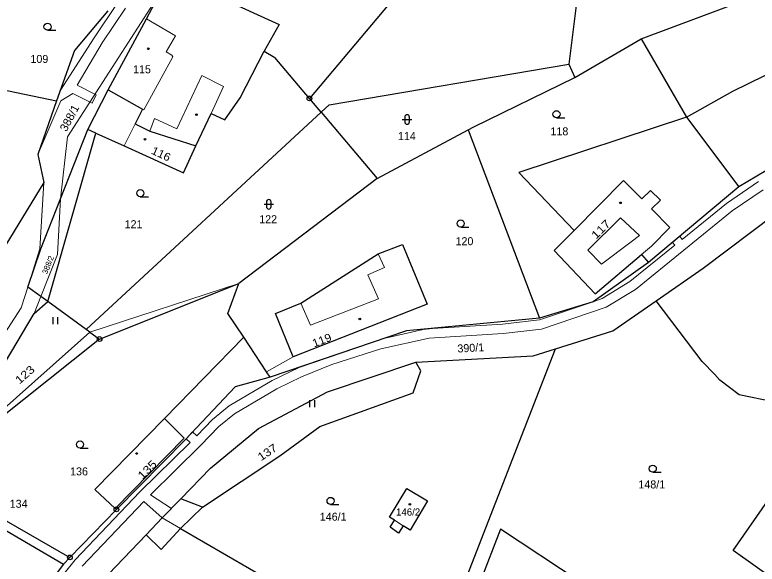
# Model space of a CAD drawing. Extents: x -504006 to -501322, y -1128098 to -1124665.
# Drawn here: x -502579.9 to -502422.2, y -1126531.9 to -1126415.1 of the extents above; entities that cross this region are included whole.
import ezdxf
from ezdxf.enums import TextEntityAlignment as Align

# ---------------------------------------------------------------- set-up
doc = ezdxf.new("R2010")
doc.units = 0
doc.header["$LTSCALE"] = 0.68
for name, color, linetype, lineweight in [('1', 7, 'Continuous', 25), ('13', 7, 'Continuous', 13), ('3', 7, 'Continuous', 25), ('4', 7, 'Continuous', 13), ('5', 7, 'Continuous', 25), ('8', 7, 'Continuous', 25)]:
    doc.layers.add(name, color=color, linetype=linetype, lineweight=lineweight)
doc.layers.add('2', color=7, linetype='Continuous')

msp = doc.modelspace()

# ---------------------------------------------------------------- linework, layer by layer
at = {"layer": '1'}
for p, q in [((-502488.63, -1126398.78), (-502517.33, -1126432.89)), ((-502459.24, -1126402.04), (-502462.2, -1126425.6)), ((-502446.8, -1126420.25), (-502404.96, -1126404.48)), ((-502546.11, -1126406.89), (-502523.76, -1126417.19)), ((-502551.92, -1126415.99), (-502549, -1126410.36)), ((-502560.18, -1126414.25), (-502562.43, -1126416.93)), ((-502560.09, -1126431.07), (-502551.92, -1126415.99)), ((-502562.43, -1126416.93), (-502567.25, -1126422.67)), ((-502523.76, -1126417.19), (-502526.92, -1126422.81)), ((-502460.9, -1126428.42), (-502446.8, -1126420.25)), ((-502446.8, -1126420.25), (-502437.18, -1126436.87)), ((-502567.25, -1126422.67), (-502571.03, -1126433.39)), ((-502532.06, -1126432.78), (-502526.92, -1126422.81)), ((-502526.92, -1126422.81), (-502524.65, -1126424.22)), ((-502517.33, -1126432.89), (-502524.65, -1126424.22)), ((-502513.12, -1126434.23), (-502462.2, -1126425.6)), ((-502462.2, -1126425.6), (-502460.9, -1126428.42)), ((-502482.37, -1126438.94), (-502460.9, -1126428.42)), ((-502582.93, -1126430.94), (-502571.03, -1126433.39)), ((-502564.42, -1126439.51), (-502560.09, -1126431.07)), ((-502560.09, -1126431.07), (-502552.75, -1126435.16)), ((-502571.03, -1126433.39), (-502575.04, -1126444.78)), ((-502535.29, -1126437.44), (-502532.06, -1126432.78)), ((-502514.85, -1126435.83), (-502517.33, -1126432.89)), ((-502552.75, -1126435.16), (-502554.32, -1126438.26)), ((-502514.85, -1126435.83), (-502513.12, -1126434.23)), ((-502564.75, -1126481.99), (-502514.85, -1126435.83)), ((-502541.42, -1126442.95), (-502538.21, -1126436.07)), ((-502538.21, -1126436.07), (-502535.29, -1126437.44)), ((-502514.85, -1126435.83), (-502502.96, -1126449.91)), ((-502554.32, -1126438.26), (-502551.25, -1126439.82)), ((-502437.18, -1126436.87), (-502472.85, -1126448.67)), ((-502437.18, -1126436.87), (-502426.09, -1126451.69)), ((-502570.21, -1126454.22), (-502564.42, -1126439.51)), ((-502562.71, -1126440.28), (-502564.42, -1126439.51)), ((-502551.25, -1126439.82), (-502541.42, -1126442.95)), ((-502502.96, -1126449.91), (-502483.59, -1126439.59)), ((-502483.59, -1126439.59), (-502482.37, -1126438.94)), ((-502483.59, -1126439.59), (-502468.46, -1126479.6)), ((-502572.9, -1126476.08), (-502562.71, -1126440.28)), ((-502562.71, -1126440.28), (-502556.71, -1126442.98)), ((-502556.71, -1126442.98), (-502544.09, -1126448.68)), ((-502544.09, -1126448.68), (-502541.42, -1126442.95)), ((-502414.39, -1126444.68), (-502426.09, -1126451.69)), ((-502575.04, -1126444.78), (-502573.73, -1126450.8)), ((-502472.85, -1126448.67), (-502461.08, -1126460.97)), ((-502573.73, -1126450.8), (-502598.36, -1126490.94)), ((-502502.96, -1126449.91), (-502532.33, -1126472.27)), ((-502426.09, -1126451.69), (-502445.3, -1126467.77)), ((-502433.67, -1126469.01), (-502413.48, -1126453.7)), ((-502574.42, -1126464.9), (-502570.21, -1126454.22)), ((-502461.08, -1126460.97), (-502465.3, -1126465.24)), ((-502577.17, -1126472.99), (-502574.42, -1126464.9)), ((-502502.72, -1126465.95), (-502497.55, -1126463.94)), ((-502497.55, -1126463.94), (-502492.28, -1126476.61)), ((-502519.13, -1126476.45), (-502502.72, -1126465.95)), ((-502465.3, -1126465.24), (-502456.61, -1126474.42)), ((-502456.61, -1126474.42), (-502446.76, -1126466.1)), ((-502446.76, -1126466.1), (-502445.3, -1126467.77)), ((-502445.3, -1126467.77), (-502457.01, -1126476.15)), ((-502443.65, -1126475.9), (-502433.67, -1126469.01)), ((-502574.4, -1126474.99), (-502577.17, -1126472.99)), ((-502561.92, -1126484.04), (-502532.33, -1126472.27)), ((-502534.63, -1126478.58), (-502532.33, -1126472.27)), ((-502575.83, -1126478.59), (-502572.9, -1126476.08)), ((-502572.9, -1126476.08), (-502574.4, -1126474.99)), ((-502564.75, -1126481.99), (-502572.9, -1126476.08)), ((-502457.01, -1126476.15), (-502468.46, -1126479.6)), ((-502452.88, -1126482.27), (-502443.65, -1126475.9)), ((-502433.88, -1126488.84), (-502443.65, -1126475.9)), ((-502524.53, -1126478.59), (-502519.13, -1126476.45)), ((-502492.28, -1126476.61), (-502520.78, -1126487.82)), ((-502581.9, -1126488.91), (-502575.83, -1126478.59)), ((-502531.27, -1126483.66), (-502534.63, -1126478.58)), ((-502520.78, -1126487.82), (-502524.53, -1126478.59)), ((-502468.46, -1126479.6), (-502496.7, -1126482.33)), ((-502563.94, -1126482.57), (-502564.75, -1126481.99)), ((-502496.7, -1126482.33), (-502525.65, -1126492.16)), ((-502465.06, -1126486.12), (-502452.88, -1126482.27)), ((-502561.92, -1126484.04), (-502598.32, -1126513.14)), ((-502563.94, -1126482.57), (-502561.92, -1126484.04)), ((-502548.11, -1126500.91), (-502531.27, -1126483.66)), ((-502526.42, -1126490.99), (-502531.27, -1126483.66)), ((-502491.56, -1126554.34), (-502465.06, -1126486.12)), ((-502469.78, -1126487.61), (-502465.06, -1126486.12)), ((-502494.74, -1126488.95), (-502469.78, -1126487.61)), ((-502431.19, -1126491.59), (-502433.88, -1126488.84)), ((-502513.47, -1126495.29), (-502494.74, -1126488.95)), ((-502493.66, -1126490.79), (-502494.74, -1126488.95)), ((-502525.65, -1126492.16), (-502526.42, -1126490.99)), ((-502495.27, -1126495.45), (-502493.66, -1126490.79)), ((-502430.09, -1126492.82), (-502431.19, -1126491.59)), ((-502525.65, -1126492.16), (-502533.07, -1126494.23)), ((-502426.04, -1126495.91), (-502430.09, -1126492.82)), ((-502533.07, -1126494.23), (-502543.67, -1126505.37)), ((-502528.11, -1126503.08), (-502513.47, -1126495.29)), ((-502515.14, -1126502.61), (-502495.27, -1126495.45)), ((-502415.56, -1126498.1), (-502426.04, -1126495.91)), ((-502562.91, -1126516.06), (-502548.11, -1126500.91)), ((-502523.58, -1126508.85), (-502515.14, -1126502.61)), ((-502538.31, -1126511.5), (-502528.11, -1126503.08)), ((-502543.67, -1126505.37), (-502558.33, -1126520.28)), ((-502540.02, -1126519.77), (-502523.58, -1126508.85)), ((-502544.62, -1126517.99), (-502538.31, -1126511.5)), ((-502598.32, -1126513.14), (-502568.21, -1126530.47)), ((-502599.01, -1126514.68), (-502569.59, -1126531.9)), ((-502558.58, -1126520.05), (-502562.91, -1126516.06)), ((-502500.28, -1126521.91), (-502496.65, -1126515.8)), ((-502496.65, -1126515.8), (-502492.22, -1126518.43)), ((-502544.62, -1126517.99), (-502548.58, -1126522.07)), ((-502540.02, -1126519.77), (-502544.62, -1126517.99)), ((-502492.22, -1126518.43), (-502495.94, -1126524.67)), ((-502427.32, -1126528.97), (-502420.01, -1126518.5)), ((-502558.33, -1126520.28), (-502568.21, -1126530.47)), ((-502558.33, -1126520.28), (-502558.58, -1126520.05)), ((-502499.22, -1126522.58), (-502500.28, -1126521.91)), ((-502552.04, -1126525.68), (-502548.58, -1126522.07)), ((-502500.16, -1126524.06), (-502499.22, -1126522.58)), ((-502544.69, -1126524.32), (-502548.79, -1126528.79)), ((-502544.69, -1126524.32), (-502524.07, -1126536.28)), ((-502498.36, -1126525.32), (-502500.16, -1126524.06)), ((-502497.37, -1126523.76), (-502498.36, -1126525.32)), ((-502495.94, -1126524.67), (-502497.37, -1126523.76)), ((-502476.73, -1126524.43), (-502488.89, -1126555.75)), ((-502415.96, -1126564.65), (-502476.73, -1126524.43)), ((-502563.11, -1126537.25), (-502552.04, -1126525.68)), ((-502548.79, -1126528.79), (-502552.04, -1126525.68)), ((-502405.98, -1126544.33), (-502427.32, -1126528.97)), ((-502568.21, -1126530.47), (-502569.59, -1126531.9)), ((-502569.59, -1126531.9), (-502578.18, -1126543.35))]:
    msp.add_line(p, q, dxfattribs=at)
msp.add_lwpolyline([(-502437.18, -1126436.87), (-502427.37, -1126431.36), (-502410.13, -1126422.93)], dxfattribs=at)
at = {"layer": '13'}
for points in [[(-502558.02, -1126412.52), (-502563.03, -1126420), (-502570.22, -1126431.1), (-502571.03, -1126433.39), (-502575.04, -1126444.78), (-502570.15, -1126433.38), (-502567.57, -1126431.85), (-502563.5, -1126433.92), (-502562.62, -1126432.12), (-502566.65, -1126430.07), (-502561.33, -1126421.06), (-502556.4, -1126413.68)], [(-502421.9, -1126450.53), (-502428.68, -1126455.2), (-502438.11, -1126462.85), (-502438.65, -1126462.2), (-502440.18, -1126463.49), (-502439.66, -1126464.11), (-502449.23, -1126471.84), (-502455.14, -1126475.44), (-502457.01, -1126476.15), (-502468.44, -1126479.97), (-502476.33, -1126480.88), (-502491.18, -1126481.8), (-502493.17, -1126481.99), (-502501.26, -1126483.88), (-502519.47, -1126490.06), (-502525.2, -1126492.86), (-502534.35, -1126498.27), (-502537.91, -1126501.16), (-502541.24, -1126504.62), (-502542.16, -1126503.79), (-502543.54, -1126505.24), (-502542.65, -1126506.04), (-502553.34, -1126516.53), (-502567.11, -1126531.01), (-502577, -1126543.32)], [(-502565.61, -1126532.33), (-502552.52, -1126518.58), (-502548.58, -1126522.07), (-502546.63, -1126520.06), (-502551.1, -1126517.14), (-502540.48, -1126506.71), (-502536.55, -1126502.64), (-502533.21, -1126499.93), (-502524.24, -1126494.62), (-502519.03, -1126492.07), (-502512.58, -1126489.47), (-502502.14, -1126486.12), (-502491.86, -1126483.89), (-502476.15, -1126482.88), (-502468.02, -1126481.93), (-502454.28, -1126477.26), (-502448.07, -1126473.48), (-502427.48, -1126456.8), (-502420.94, -1126452.29)]]:
    msp.add_lwpolyline(points, dxfattribs=at)
at = {"layer": '3'}
for p, q in [((-502572.963, -1126418.4), (-502571.213, -1126418.4)), ((-502497.581, -1126437.371), (-502495.579, -1126437.371)), ((-502497.081, -1126436.871), (-502497.081, -1126437.872)), ((-502496.079, -1126437.872), (-502496.079, -1126436.871)), ((-502464.823, -1126437), (-502463.073, -1126437)), ((-502553.253, -1126453.78), (-502551.503, -1126453.78)), ((-502526.951, -1126455.401), (-502524.949, -1126455.401)), ((-502526.451, -1126454.901), (-502526.451, -1126455.902)), ((-502525.449, -1126455.902), (-502525.449, -1126454.901)), ((-502485.183, -1126460.23), (-502483.433, -1126460.23)), ((-502571.771, -1126480.88), (-502571.771, -1126479.38)), ((-502570.77, -1126480.88), (-502570.77, -1126479.38)), ((-502517.201, -1126498.54), (-502517.201, -1126497.04)), ((-502516.2, -1126498.54), (-502516.2, -1126497.04)), ((-502566.063, -1126507.21), (-502564.313, -1126507.21)), ((-502444.363, -1126512.35), (-502442.613, -1126512.35)), ((-502512.833, -1126519.2), (-502511.083, -1126519.2))]:
    msp.add_line(p, q, dxfattribs=at)
for centre in [(-502572.9629, -1126417.6498), (-502464.8229, -1126436.2498), (-502553.2529, -1126453.0298), (-502485.1829, -1126459.4798), (-502566.0629, -1126506.4598), (-502444.3629, -1126511.5998), (-502512.8329, -1126518.4498)]:
    msp.add_circle(centre, 0.75, dxfattribs=at)
for centre, start, end in [((-502496.58, -1126436.8709), 0, 180), ((-502496.58, -1126437.8709), 180, 359.98789), ((-502525.95, -1126454.9009), 0, 180), ((-502525.95, -1126455.9009), 180, 359.98789)]:
    msp.add_arc(centre, 0.5, start, end, dxfattribs=at)
at = {"layer": '4'}
for p, q in [((-502549, -1126410.36), (-502568.73, -1126441.07)), ((-502551.92, -1126415.99), (-502545.75, -1126419.56)), ((-502545.75, -1126419.56), (-502547.73, -1126422.99)), ((-502546.36, -1126424.03), (-502552.53, -1126435.29)), ((-502547.73, -1126422.99), (-502546.57, -1126423.72)), ((-502546.57, -1126423.72), (-502546.36, -1126424.03)), ((-502545.49, -1126439.37), (-502540.16, -1126428.05)), ((-502540.16, -1126428.05), (-502535.54, -1126430.33)), ((-502535.54, -1126430.33), (-502538.21, -1126436.07)), ((-502552.53, -1126435.29), (-502552.75, -1126435.16)), ((-502556.71, -1126442.98), (-502554.32, -1126438.26)), ((-502551.25, -1126439.82), (-502550.21, -1126437.15)), ((-502550.21, -1126437.15), (-502545.49, -1126439.37)), ((-502568.73, -1126441.07), (-502570.21, -1126454.22)), ((-502574.57, -1126464.88), (-502573.73, -1126450.8)), ((-502461.08, -1126460.97), (-502450.62, -1126450.36)), ((-502450.62, -1126450.36), (-502446.72, -1126454.27)), ((-502446.72, -1126454.27), (-502444.82, -1126452.43)), ((-502444.82, -1126452.43), (-502442.76, -1126454.52)), ((-502570.21, -1126454.22), (-502570.86, -1126466.05)), ((-502442.76, -1126454.52), (-502444.63, -1126456.37)), ((-502444.63, -1126456.37), (-502440.71, -1126460.31)), ((-502458.16, -1126465.16), (-502451.21, -1126458.28)), ((-502451.21, -1126458.28), (-502447.16, -1126462)), ((-502440.71, -1126460.31), (-502444.66, -1126464.32)), ((-502447.16, -1126462), (-502448.94, -1126463.35)), ((-502448.94, -1126463.35), (-502455.29, -1126468.16)), ((-502577.17, -1126472.99), (-502574.57, -1126464.88)), ((-502455.29, -1126468.16), (-502458.16, -1126465.16)), ((-502444.66, -1126464.32), (-502446.76, -1126466.1)), ((-502570.86, -1126466.05), (-502574.4, -1126474.99)), ((-502501.4, -1126468.85), (-502502.72, -1126465.95)), ((-502504.89, -1126470.42), (-502501.4, -1126468.85)), ((-502502.61, -1126475.51), (-502504.89, -1126470.42)), ((-502578.58, -1126477.39), (-502577.17, -1126472.99)), ((-502532.33, -1126472.27), (-502563.94, -1126482.57)), ((-502574.4, -1126474.99), (-502575.83, -1126478.59)), ((-502517.06, -1126481.1), (-502502.61, -1126475.51)), ((-502584.47, -1126486.55), (-502578.58, -1126477.39)), ((-502519.13, -1126476.45), (-502517.06, -1126481.1)), ((-502598.32, -1126513.14), (-502563.94, -1126482.57)), ((-502526.42, -1126490.99), (-502520.78, -1126487.82)), ((-502548.11, -1126500.91), (-502543.92, -1126505.12)), ((-502543.92, -1126505.12), (-502558.58, -1126520.05)), ((-502544.69, -1126524.32), (-502540.02, -1126519.77)), ((-502548.58, -1126522.07), (-502544.69, -1126524.32)), ((-502497.37, -1126523.76), (-502499.22, -1126522.58))]:
    msp.add_line(p, q, dxfattribs=at)
at = {"layer": '5'}
for centre in [(-502551.5468, -1126422.3392), (-502541.3268, -1126436.3592), (-502552.2368, -1126441.5692), (-502451.2368, -1126455.0892), (-502506.6168, -1126479.7792), (-502554.0368, -1126508.3792), (-502495.9868, -1126519.1992)]:
    msp.add_circle(centre, 0.175, dxfattribs=at)
at = {"layer": '8'}
for centre, radius in [((-502517.33, -1126432.8899), 0.5), ((-502517.33, -1126432.8899), 0.0303), ((-502561.92, -1126484.0399), 0.5), ((-502561.92, -1126484.0399), 0.0303), ((-502558.33, -1126520.2799), 0.5), ((-502558.33, -1126520.2799), 0.0303), ((-502568.21, -1126530.4699), 0.5), ((-502568.21, -1126530.4699), 0.0303)]:
    msp.add_circle(centre, radius, dxfattribs=at)

# ---------------------------------------------------------------- texts
at = {"layer": '2'}
for s, height, p in [('109', 1.7, (-502574.699, -1126425.345)), ('115', 1.7, (-502552.889, -1126427.545)), ('118', 1.7, (-502464.209, -1126440.735)), ('114', 1.7, (-502496.619, -1126441.745)), ('121', 1.7, (-502554.689, -1126460.485)), ('122', 1.7, (-502526.089, -1126459.425)), ('120', 1.7, (-502484.379, -1126464.095)), ('136', 1.7, (-502566.269, -1126513.035)), ('148/1', 1.7, (-502444.58, -1126515.805)), ('146/2', 1.53, (-502496.35, -1126521.582)), ('146/1', 1.7, (-502512.27, -1126522.665))]:
    msp.add_text(s, height=height, dxfattribs=at).set_placement(p, align=Align.CENTER)
for s, rotation, width, p in [('388/1', 62, 1.05, (-502567.5564, -1126437.4456)), ('116', 335, 1.1, (-502549.1867, -1126445.4602)), ('117', 45, 1.2, (-502454.7925, -1126461.3235)), ('119', 21, 1.1, (-502514.3826, -1126485.0868)), ('123', 41, 1.2, (-502577.2271, -1126492.2538)), ('137', 34, 1.15, (-502525.7893, -1126508.8184)), ('135', 45, 1.2, (-502551.1925, -1126512.4235))]:
    msp.add_text(s, height=1.7, rotation=rotation, dxfattribs=dict(at, width=width)).set_placement(p, align=Align.CENTER)
for s, height, rotation, p in [('388/2', 1.2, 68, (-502572.3048, -1126468.5073)), ('390/1', 1.7, 3, (-502482.9945, -1126486.7724))]:
    msp.add_text(s, height=height, rotation=rotation, dxfattribs=at).set_placement(p, align=Align.CENTER)
msp.add_text('134', height=1.7, dxfattribs=at).set_placement((-502581, -1126519.915))

doc.saveas('drawing.dxf')
